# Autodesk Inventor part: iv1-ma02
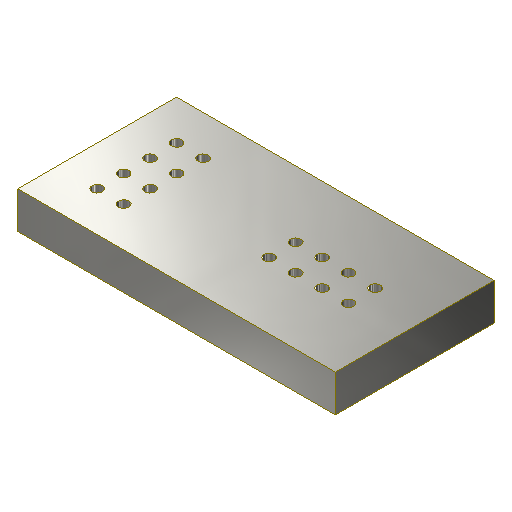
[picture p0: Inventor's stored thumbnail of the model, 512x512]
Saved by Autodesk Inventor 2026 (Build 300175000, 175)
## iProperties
Created: 2004-10
Part Number: iv1-ma02
Document SubType Name: Modeling
Designer: Lars Bertram Pedersen
Manufacturer: Standard
Standards Organization: Custom
Material: Steel, Mild
Density: 7.85 g/cm^3
Appearance: Silver
Mass: 12255.2 g
Surface Area: 1267.36 cm^2
Volume: 1561.18 cm^3
Description: Den store klods....
Stock Number: 1000
Author: Lars Bertram Pedersen
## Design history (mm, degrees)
sketch "Sketch1"
  geometry: L1 (0, 0)-(300, 0); L2 (300, 0)-(300, 150); L3 (300, 150)-(0, 150); L4 (0, 150)-(0, 0); 1 further point
  constraints: 8 end point, 2 parallel, 1 coincident, 1 horizontal, 1 perpendicular
  dimensions: "d0" = 300 distance of L1.start L1.end; "d1" = 150 distance of L3.end L1.start
extrude "Extrusion1" new body sketch "Sketch1" distance "d2" = 35; taper "d3" = 0 deg
hole "Hole1" diameter "d6" = 10; stored, may be unused: countersink angle "d10" = 90 deg, drill point angle "d12" = 118 deg; dims "d4" = 37.5, "d5" = 37.5, "d7" = 6, "d8" = 4, "d9" = 2, "d11" = 10
pattern_linear "Rectangular Pattern1" dims "d15" = 25, "d18" = 25
hole "Hole2" diameter "d21" = 10; stored, may be unused: countersink angle "d25" = 90 deg, drill point angle "d27" = 118 deg; dims "d19" = 62.5, "d20" = 50, "d22" = 6, "d23" = 4, "d24" = 2, "d26" = 10
pattern_linear "Rectangular Pattern2" dims "d30" = 25, "d33" = 25
body "Solid1"
